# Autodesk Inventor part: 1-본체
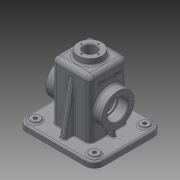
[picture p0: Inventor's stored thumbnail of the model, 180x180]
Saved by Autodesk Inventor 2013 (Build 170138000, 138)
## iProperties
Created: 2016-06
Part Number: 1-본체
Material: Generic
Document SubType Name: Modeling
Designer: k
Density: 1 g/cm^3
Author: k
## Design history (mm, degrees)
sketch "스케치1"
  geometry: L1 (-65, -57.5)-(65, -57.5); L2 (65, -57.5)-(65, 57.5); L3 (65, 57.5)-(-65, 57.5); L4 (-65, 57.5)-(-65, -57.5); L5 (-65, -57.5)-(65, 57.5); L6 (65, -57.5)-(-65, 57.5); 1 further point
  constraints: 12 end point, 2 midpoint, 2 parallel, 1 horizontal, 1 perpendicular
  dimensions: "d0" = 130 distance of L2.end L3.end; "d2" = 115 distance of L1.end L2.end
extrude "돌출1" new body sketch "스케치1" distance "d3" = 12; taper "d4" = 0 deg
sketch "스케치2"
  geometry: L1 (-32.5, 32.5)-(32.5, 32.5); L2 (32.5, 32.5)-(32.5, -32.5); L3 (32.5, -32.5)-(-32.5, -32.5); L4 (-32.5, -32.5)-(-32.5, 32.5); L5 (-32.5, 32.5)-(32.5, -32.5); L6 (32.5, 32.5)-(-32.5, -32.5); 1 further point
  constraints: 12 end point, 2 midpoint, 2 parallel, 2 perpendicular, 1 horizontal
  dimensions: "d5" = 65 distance of L1.start L1.end
extrude "돌출2" join sketch "스케치2" distance "d7" = 98; taper "d8" = 0 deg
feature "쉘1" dims "d9" = 12, "d10" = 5
sketch "스케치3"
  geometry: L1 (12, -25)-(12, 90) reference; C1 r 27.5 at (-43, 32.5); 1 further point
  constraints: 1 centre point
  dimensions: "d11" = 55 distance from line of C1.centre L1; "d12" = 55 diameter of C1
extrude "돌출3" join sketch "스케치3" distance "d13" = 15; taper "d14" = 0 deg
node "작업 평면1"
sketch "스케치4"
  geometry: C1 r 20 at (0, 0); 1 further point
  constraints: 1 centre point, 1 coincident
  dimensions: "d16" = 40 diameter of C1
extrude "돌출4" join sketch "스케치4" stored distance "d17" = 15; taper "d18" = 5 deg
sketch "스케치5"
  geometry: L1 (57.5, 12)-(-57.5, 12) reference; L2 (32.5, 12)-(32.5, 110) reference; L3 (47.5, 12)-(32.5, 97.069); L4 (57.5, 0)-(57.5, 12) reference; 1 further point
  constraints: 2 end point, 2 point on line
  dimensions: "d19" = 10 distance from line of L3.start L4; "d20" = 10 deg angle of L3 L4
feature "리브1" sketch "스케치5" dims "d21" = 1, "d22" = 10, "d23" = 0, "d24" = 0, "d25" = 1, "d26" = 1
sketch "스케치6"
  geometry: L1 (-32.5, 27.5)-(-47.5, 27.5) reference; L2 (65, 12)-(-65, 12) reference; L3 (-32.5, 12)-(-32.5, 110) reference; L4 (-42.5, 12)-(-42.5, 27.5); L5 (-27.5, 0)-(-27.5, 105) reference; 1 further point
  constraints: 2 end point, 2 point on line, 1 parallel
  dimensions: "d28" = 15 distance between parallel lines of L5 L4
feature "리브2" sketch "스케치6" dims "d29" = 1, "d30" = 6, "d31" = 0, "d32" = 0, "d33" = 1, "d34" = 1
fillet "모깎기1" dims "d35" = 15
sketch "스케치7"
  geometry: L1 (-50, 57.5)-(50, 57.5) reference; L2 (-65, -42.5)-(-65, 42.5) reference; L3 (50, -57.5)-(-50, -57.5) reference; L4 (65, 42.5)-(65, -42.5) reference; L5 (60, 42.5)-(60, -42.5); L6 (50, -52.5)-(-50, -52.5); L7 (-60, -42.5)-(-60, 42.5); L8 (-50, 52.5)-(50, 52.5); A1 r 15 centre (50, 42.5) between (65, 42.5) and (50, 57.5) reference; A2 r 15 centre (-50, 42.5) between (-50, 57.5) and (-65, 42.5) reference; A3 r 15 centre (-50, -42.5) between (-65, -42.5) and (-50, -57.5) reference; A4 r 15 centre (50, -42.5) between (50, -57.5) and (65, -42.5) reference; A5 r 10 centre (50, 42.5) between (60, 42.5) and (50, 52.5); A6 r 10 centre (50, -42.5) between (50, -52.5) and (60, -42.5); A7 r 10 centre (-50, -42.5) between (-60, -42.5) and (-50, -52.5); A8 r 10 centre (-50, 42.5) between (-50, 52.5) and (-60, 42.5); 1 further point
  constraints: 8 end point, 8 point on circle, 4 centre point, 7 other
  dimensions: "d36" = 5 distance between parallel lines of L8 L1
extrude "돌출5" cut sketch "스케치7" distance "d37" = 2; taper "d38" = 0 deg
sketch "스케치8"
  geometry: C1 r 7.5 at (-50, 42.5); C2 r 7.5 at (50, 42.5); C3 r 7.92 at (50, -42.5); C4 r 7.92 at (-50, -42.5); A1 r 15 centre (-50, 42.5) between (-50, 57.5) and (-65, 42.5) reference; A2 r 15 centre (-50, -42.5) between (-65, -42.5) and (-50, -57.5) reference; A3 r 15 centre (50, -42.5) between (50, -57.5) and (65, -42.5) reference; A4 r 15 centre (50, 42.5) between (65, 42.5) and (50, 57.5) reference; 1 further point
  constraints: 4 centre point, 4 coincident, 2 equal radius
  dimensions: "d39" = 15 diameter of C1
extrude "돌출6" join sketch "스케치8" distance "d40" = 3; taper "d41" = 0 deg
fillet "모깎기2" dims "d42" = 8
fillet "모깎기3" dims "d43" = 8
fillet "모깎기4" dims "d44" = 3
fillet "모깎기5" dims "d45" = 3
fillet "모깎기6" dims "d46" = 3
fillet "모깎기7" dims "d47" = 3
fillet "모깎기8" dims "d48" = 3
fillet "모깎기9" dims "d49" = 3
fillet "모깎기10" dims "d50" = 3
fillet "모깎기11" dims "d51" = 3
fillet "모깎기12" dims "d52" = 3
fillet "모깎기13" dims "d53" = 3
fillet "모깎기14" dims "d54" = 3
hole "구멍1" diameter "d57" = 21; stored, may be unused: countersink angle "d61" = 90 deg, drill point angle "d63" = 118 deg; dims "d55" = 10, "d56" = 10, "d58" = 6, "d59" = 4, "d60" = 2, "d62" = 8
hole "구멍2" diameter "d66" = 30; stored, may be unused: countersink angle "d70" = 90 deg, drill point angle "d72" = 118 deg; dims "d64" = 10, "d65" = 10, "d67" = 30, "d68" = 35, "d69" = 17, "d71" = 8
hole "구멍3" diameter "d75" = 30; stored, may be unused: countersink angle "d79" = 90 deg, drill point angle "d81" = 118 deg; dims "d73" = 10, "d74" = 10, "d76" = 30, "d77" = 35, "d78" = 17, "d80" = 8
fillet "모깎기15" dims "d82" = 3
fillet "모깎기16" dims "d83" = 1
chamfer "모따기1" distance "d84" = 1; stored, may be unused: second distance "d85" = 2, angle "d86" = 45 deg
fillet "모깎기17" dims "d87" = 0.3
fillet "모깎기18" dims "d88" = 0.3
hole "구멍4" diameter "d91" = 6; stored, may be unused: countersink angle "d95" = 90 deg, drill point angle "d97" = 118 deg; dims "d89" = 10, "d90" = 10, "d92" = 30, "d93" = 35, "d94" = 17, "d96" = 8
hole "구멍5" diameter "d100" = 6; stored, may be unused: countersink angle "d104" = 90 deg, drill point angle "d106" = 118 deg; dims "d98" = 10, "d99" = 10, "d101" = 30, "d102" = 35, "d103" = 17, "d105" = 8
hole "구멍6" diameter "d109" = 6; stored, may be unused: countersink angle "d113" = 90 deg, drill point angle "d115" = 118 deg; dims "d107" = 10, "d108" = 10, "d110" = 30, "d111" = 35, "d112" = 17, "d114" = 8
hole "구멍7" diameter "d118" = 6; stored, may be unused: countersink angle "d122" = 90 deg, drill point angle "d124" = 118 deg; dims "d116" = 10, "d117" = 10, "d119" = 30, "d120" = 35, "d121" = 17, "d123" = 8
sketch "스케치9"
  geometry: L1 (-18, 4.5)-(-18, 44.5) reference; L2 (0, -8)-(89, -8) reference; 2 further points
  constraints: 1 other
  dimensions: "d125" = 26 distance from line of point (8, 24.5) L1; "d126" = 32.5 distance from line of point (8, 24.5) L2
feature "엠보싱1" sketch "스케치9" dims "d127" = 0.5, "d128" = 0
sketch "스케치10"
  geometry: C1 r 20 at (0, 0) reference; 1 further point
  dimensions: "d129" = 14.5 distance of C1.centre point (0, 14.5)
hole "구멍8" sketch "스케치10" at (0, 14.5) diameter "d130" = 2.459; stored, may be unused: countersink angle "d134" = 82 deg, drill point angle "d136" = 118 deg; dims "d131" = 7, "d132" = 3.023, "d133" = 17, "d135" = 9
sketch "스케치11"
  geometry: C1 r 17.5 at (0, 0) reference; 2 further points
  constraints: 1 horizontal alignment
  dimensions: "d140" = 21 distance of C1.centre point (-21, 0)
hole "구멍9" sketch "스케치11" at (-21, 0) diameter "d141" = 3.242; stored, may be unused: countersink angle "d145" = 82 deg, drill point angle "d147" = 118 deg; dims "d142" = 8, "d143" = 3.023, "d144" = 17, "d146" = 10
sketch "스케치12"
  geometry: C1 r 17.5 at (0, 0) reference; 2 further points
  constraints: 1 horizontal alignment
  dimensions: "d151" = 21 distance of point (21, 0) C1.centre
hole "구멍10" sketch "스케치12" at (21, 0) diameter "d152" = 3.242; stored, may be unused: countersink angle "d156" = 82 deg, drill point angle "d158" = 118 deg; dims "d153" = 8, "d154" = 3.023, "d155" = 17, "d157" = 10
chamfer "모따기2" distance "d162" = 1; stored, may be unused: second distance "d163" = 2, angle "d164" = 45 deg
chamfer "모따기3" distance "d165" = 1; stored, may be unused: second distance "d166" = 2, angle "d167" = 45 deg
fillet "모깎기19" dims "d168" = 3
fillet "모깎기20" dims "d169" = 3
node "솔리드1"
mirror "대칭1"
mirror "대칭2"
mirror "대칭3"
pattern_circular "원형 패턴1" dims angle "d138" = 360 deg
pattern_circular "원형 패턴2" dims angle "d149" = 360 deg
pattern_circular "원형 패턴3" dims angle "d160" = 360 deg
